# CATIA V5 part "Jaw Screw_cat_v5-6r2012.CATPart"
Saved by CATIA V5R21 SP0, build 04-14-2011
Part number: Jaw Screw
Bounding box of the stored display mesh (mm): x -9 to 9, y 0 to 138, z -8.948 to 8.97
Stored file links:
  D:\CATIA V5R21 E-RESOURCES\CATIA-V5R21\catia-v5r21-Tut\c16-catia-v5r21-tut\c16-catia-v5r21-tut01\Jaw Screw_cat_v5r21.CATPart
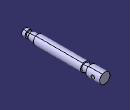
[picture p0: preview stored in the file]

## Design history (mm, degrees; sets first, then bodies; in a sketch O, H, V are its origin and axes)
Body1 (main body)
  Sketch1 on yz-plane, origin (0, 0, 0), H (0, 1, 0), V (0, 0, 1)
    line L1 (0, 0) -> (0, 6)
    line L2 (0, 6) -> (6, 6)
    line L3 (6, 6) -> (6, 4)
    line L4 (6, 4) -> (11, 4)
    line L5 (11, 4) -> (11, 6)
    point P5 (11, 6)
    line L6 (11, 6) -> (22, 6)
    line L7 (22, 6) -> (22, 8)
    line L8 (22, 8) -> (104, 8)
    line L9 (104, 8) -> (104, 6)
    point P9 (104, 6)
    line L10 (104, 6) -> (114, 6)
    line L11 (114, 6) -> (114, 9)
    line L12 (114, 9) -> (138, 9)
    line L13 (138, 9) -> (138, 0)
    point P13 (138, 0)
    line L14 (138, 0) -> (0, 0)
    distance L2 L14 = 6
    distance L8 L14 = 8
    distance L12 L14 = 9
    length L2 = 6
    length L4 = 5
    length L8 = 82
    length L10 = 10
    length L12 = 24
    length L14 = 138
    distance L4 L14 = 4
    vertical: L1 V, L3 V, L5 V, L7 V, L9 V, L11 V, L13 V
    horizontal: L2 H, L4 H, L6 H, L8 H, L10 H, L12 H, L14 H
    coincidence: P5 L2, P9 L6, P13 H
  Shaft1: profile Sketch1, axis edge of Sketch1, angle 360
  Sketch2 on yz-plane, origin (0, 0, 0), H (0, 1, 0), V (0, 0, 1)
    circle A1 centre (126, 0) radius 3
    point P1 (126, 0)
    radius A1 = 3
    distance P1 V = 126
    coincidence: P1 H
  Pocket1: profile Sketch2, direction (-1, 0, 0), length 20, mirrored extent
